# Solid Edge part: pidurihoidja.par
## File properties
Title: pidurihoidja
Author: Stella-Marii
Template: iso metric part.par
Last saved by: Stella-Marii
Revision: 5
Application: Solid Edge
Density: 1024,000 kg/m^3
Accuracy: 0,990
Username: Stella-Marii
Document Number: 29
Material: ABS Plastic, high impact
Face Style: Red
Fill Style: ANSI34(Plastic)
Virtual Style: Red (Shiny)
Grouping: Non-metals\Plastics
LibraryName: Materials
Coef. of Thermal Exp: 9e-05
Thermal Conductivity: 0.2
Specific Heat: 0.0
Modulus of Elasticity: 1378951400.0
Poisson's Ratio: 0.4
Yield Stress: 31026406.5
Ultimate Stress: 0.0
Elongation: 0.0
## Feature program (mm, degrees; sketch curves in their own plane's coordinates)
sketch for "unnamed Protrusion 1" plane through (0, 0, 0) normal (0, 0, 1) x-axis (1, 0, 0)
  line (-32.8682, 0) -> (32.8682, 0)
  bspline degree 3 poles (32.8682, 0) (28.926, 9.3573) (17.6811, 22.6938) (-6.4257, 32.91) (-16.6374, 28.1915) (-19.5517, 26.8127) knots 0 0.4757 0.8677 1 multiplicities 4 1 1 4
  line (-19.5517, 26.8127) -> (-32.8682, 9.6123)
  line (-32.8682, 9.6123) -> (-32.8682, 0)
extrude "unnamed Protrusion 1" add finite 10 symmetric
sketch for "unnamed Cutout 1" plane through (-32.8682, 6.5316, 0) normal (-1, 0, 0) x-axis (0, 0, 1)
  circle centre (0, -17.4094) radius 11.9719
extrude "unnamed Cutout 1" cut finite 199.3011 symmetric
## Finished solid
Body 1: solid body, 6 faces, 12 edges, 8 vertices.
  Faces by surface: plane 4, cylinder 1, swept 1
  Edges by curve: line 8, spline 2, circle 1, intersection 1
Bounding box of the edges (mm; curved faces can reach further): 65.736 x 30.297 x 10.000, from (-32.8682, 0, -5) to (32.8682, 30.2969, 5).
Cylindrical faces by radius (mm): R11.9719 x1
Planar faces by outward normal: +z 1, -x 1, -z 1, oblique 1
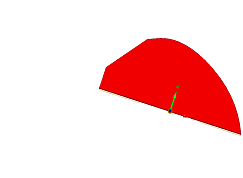
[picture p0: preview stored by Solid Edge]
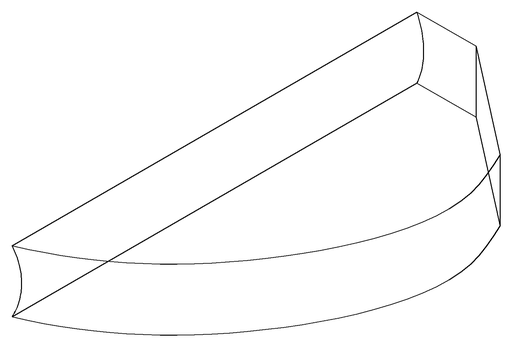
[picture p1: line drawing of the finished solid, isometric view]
